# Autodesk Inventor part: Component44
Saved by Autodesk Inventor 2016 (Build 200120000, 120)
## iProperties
Created: 2016-09
Part Number: Component44
Material: Generic
Document SubType Name: Modeling
Designer: Administrator
Appearance: Generic
Author: Administrator
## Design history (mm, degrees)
feature "Body1"
body "Solid1"
